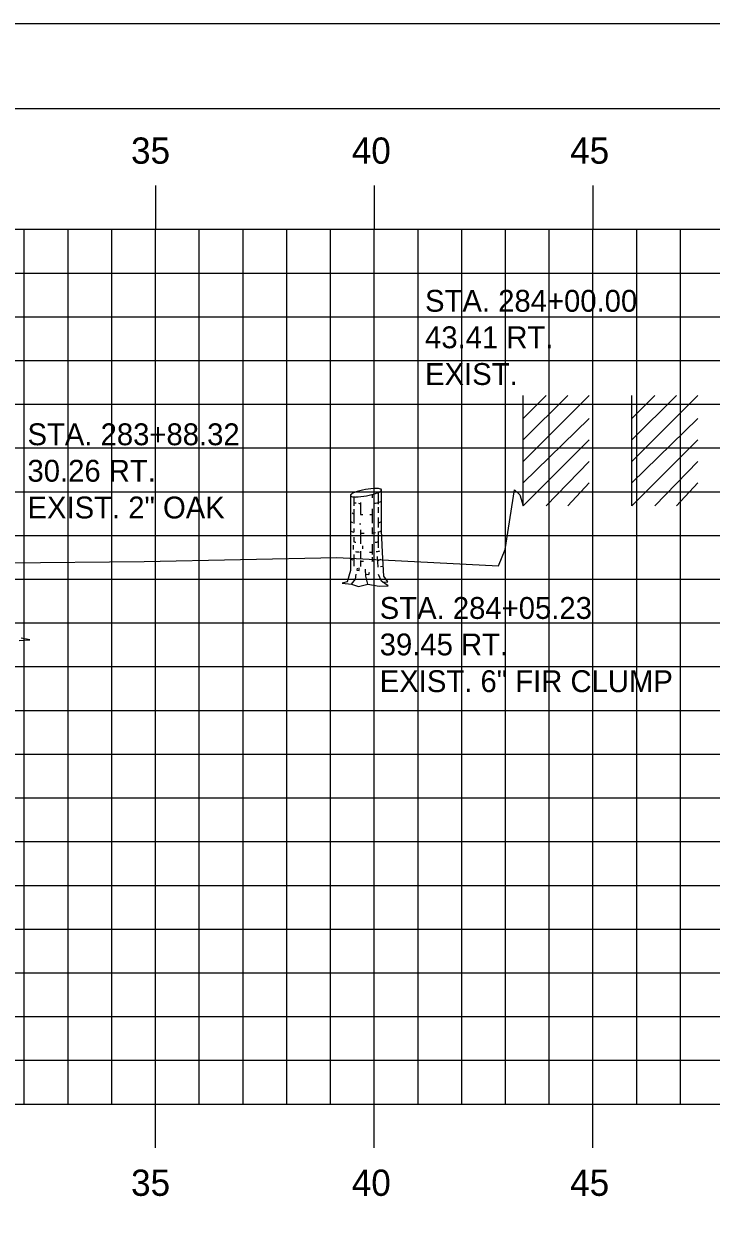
# Model space of a CAD drawing. Extents: x 856235 to 856405, y 366268 to 366378.
# Drawn here: x 856349.77 to 856365.48, y 366350.83 to 366378.18 of the extents above; entities that cross this region are included whole.
import ezdxf

# ---------------------------------------------------------------- set-up
doc = ezdxf.new("R2010")
doc.units = 0
for name, color, linetype in [('BORDER', 7, 'Continuous'), ('D_Text_Monospaced', 7, 'Continuous'), ('H_V ANNOTATION', 7, 'Continuous'), ('MAJOR', 7, 'Continuous'), ('MINOR', 7, 'Continuous'), ('PLOT BOUNDARY', 7, 'Continuous'), ('S_Buildings', 7, 'Continuous'), ('S_Roadway_Centerline', 7, 'Continuous'), ('S_Trees_Conifer_NonPay', 7, 'Continuous'), ('S_Trees_Decid_Pay', 7, 'Continuous')]:
    doc.layers.add(name, color=color, linetype=linetype)

msp = doc.modelspace()

# ---------------------------------------------------------------- linework, layer by layer
at = {"layer": 'BORDER'}
msp.add_line((856402.781, 366376.236), (856242.781, 366376.236), dxfattribs=at)
at = {"layer": 'MAJOR'}
for p, q in [((856352.781, 366374.483), (856352.781, 366373.481)), ((856357.781, 366374.483), (856357.781, 366373.481)), ((856362.781, 366374.483), (856362.781, 366373.481)), ((856247.781, 366373.481), (856387.781, 366373.481)), ((856247.781, 366373.481), (856387.781, 366373.481)), ((856352.781, 366353.481), (856352.781, 366373.481)), ((856357.781, 366353.481), (856357.781, 366373.481)), ((856362.781, 366353.481), (856362.781, 366373.481)), ((856247.781, 366368.481), (856387.781, 366368.481)), ((856247.781, 366363.481), (856387.781, 366363.481)), ((856247.781, 366358.481), (856387.781, 366358.481)), ((856247.781, 366353.481), (856387.781, 366353.481)), ((856247.781, 366353.481), (856387.781, 366353.481)), ((856352.781, 366352.479), (856352.781, 366353.481)), ((856357.781, 366352.479), (856357.781, 366353.481)), ((856362.781, 366352.479), (856362.781, 366353.481))]:
    msp.add_line(p, q, dxfattribs=at)
at = {"layer": 'MINOR'}
for p, q in [((856349.781, 366353.481), (856349.781, 366373.481)), ((856350.781, 366353.481), (856350.781, 366373.481)), ((856351.781, 366353.481), (856351.781, 366373.481)), ((856353.781, 366353.481), (856353.781, 366373.481)), ((856354.781, 366353.481), (856354.781, 366373.481)), ((856355.781, 366353.481), (856355.781, 366373.481)), ((856356.781, 366353.481), (856356.781, 366373.481)), ((856358.781, 366353.481), (856358.781, 366373.481)), ((856359.781, 366353.481), (856359.781, 366373.481)), ((856360.781, 366353.481), (856360.781, 366373.481)), ((856361.781, 366353.481), (856361.781, 366373.481)), ((856363.781, 366353.481), (856363.781, 366373.481)), ((856364.781, 366353.481), (856364.781, 366373.481)), ((856247.781, 366372.481), (856387.781, 366372.481)), ((856247.781, 366371.481), (856387.781, 366371.481)), ((856247.781, 366370.481), (856387.781, 366370.481)), ((856247.781, 366369.481), (856387.781, 366369.481)), ((856247.781, 366367.481), (856387.781, 366367.481)), ((856247.781, 366366.481), (856387.781, 366366.481)), ((856247.781, 366365.481), (856387.781, 366365.481)), ((856247.781, 366364.481), (856387.781, 366364.481)), ((856247.781, 366362.481), (856387.781, 366362.481)), ((856247.781, 366361.481), (856387.781, 366361.481)), ((856247.781, 366360.481), (856387.781, 366360.481)), ((856247.781, 366359.481), (856387.781, 366359.481)), ((856247.781, 366357.481), (856387.781, 366357.481)), ((856247.781, 366356.481), (856387.781, 366356.481)), ((856247.781, 366355.481), (856387.781, 366355.481)), ((856247.781, 366354.481), (856387.781, 366354.481))]:
    msp.add_line(p, q, dxfattribs=at)
at = {"layer": 'PLOT BOUNDARY'}
msp.add_lwpolyline([(856234.688, 366268.177), (856404.688, 366268.177), (856404.688, 366378.177), (856234.688, 366378.177)], close=True, dxfattribs=at)
at = {"layer": 'S_Buildings'}
for p, q in [((856361.186, 366367.157), (856361.186, 366369.683)), ((856361.186, 366368.174), (856362.696, 366369.683)), ((856361.186, 366368.666), (856362.203, 366369.683)), ((856361.186, 366369.158), (856361.711, 366369.683)), ((856363.672, 366367.157), (856363.672, 366369.683)), ((856363.672, 366368.174), (856365.182, 366369.683)), ((856363.672, 366368.666), (856364.69, 366369.683)), ((856363.672, 366369.158), (856364.197, 366369.683)), ((856361.186, 366367.682), (856362.696, 366369.158)), ((856363.672, 366367.682), (856365.182, 366369.158)), ((856361.186, 366367.157), (856362.696, 366368.666)), ((856363.672, 366367.157), (856365.182, 366368.666)), ((856361.711, 366367.157), (856362.696, 366368.174)), ((856364.197, 366367.157), (856365.182, 366368.174)), ((856362.203, 366367.157), (856362.696, 366367.682)), ((856364.69, 366367.157), (856365.182, 366367.682))]:
    msp.add_line(p, q, dxfattribs=at)
at = {"layer": 'S_Roadway_Centerline'}
msp.add_lwpolyline([(856328.954, 366363.708), (856329.863, 366363.704), (856333.689, 366363.627), (856333.914, 366363.825), (856333.97, 366363.951), (856334.308, 366364.232), (856334.342, 366364.246), (856335.581, 366364.715), (856337.467, 366365.5), (856349.355, 366365.853), (856352.52, 366365.887), (856356.926, 366365.979), (856360.623, 366365.787), (856360.773, 366366.162), (856360.989, 366367.526), (856361.112, 366367.411), (856361.186, 366367.157)], dxfattribs=at)
at = {"layer": 'S_Trees_Conifer_NonPay'}
for p, q in [((856357.314, 366367.362), (856357.314, 366367.156)), ((856357.47, 366367.237), (856357.47, 366366.964)), ((856357.732, 366367.417), (856357.732, 366367.338)), ((856357.314, 366367.084), (856357.314, 366366.752)), ((856357.732, 366367.089), (856357.732, 366366.763)), ((856357.867, 366367.128), (856357.867, 366366.998)), ((856357.314, 366366.638), (856357.314, 366366.559)), ((856357.732, 366366.662), (856357.732, 366366.509)), ((856357.867, 366366.889), (856357.867, 366366.662)), ((856357.314, 366366.445), (856357.314, 366366.336)), ((856357.47, 366366.61), (856357.47, 366366.292)), ((856357.867, 366366.571), (856357.867, 366366.195)), ((856357.297, 366366.258), (856357.297, 366366.161)), ((856357.47, 366366.122), (856357.47, 366365.962)), ((856357.512, 366366.247), (856357.512, 366366.177)), ((856357.732, 366366.28), (856357.732, 366366.047)), ((856357.314, 366366.047), (856357.314, 366365.779)), ((856357.47, 366365.905), (856357.47, 366365.773)), ((856357.732, 366365.985), (856357.732, 366365.899)), ((856357.848, 366366.002), (856357.866, 366365.756)), ((856357.927, 366365.773), (856357.988, 366365.78))]:
    msp.add_line(p, q, dxfattribs=at)
for points in [[(856357.867, 366367.458), (856357.867, 366367.361), (856357.867, 366367.196)], [(856357.978, 366365.412), (856358.094, 366365.422), (856358.002, 366365.547), (856357.969, 366366.088), (856357.948, 366366.605), (856357.948, 366367.524)], [(856357.235, 366367.396), (856357.235, 366365.678), (856357.165, 366365.422), (856357.046, 366365.387), (856357.262, 366365.371), (856357.422, 366365.313), (856357.631, 366365.371), (856357.894, 366365.324), (856358.1, 366365.33), (856357.948, 366365.433), (856357.877, 366365.586)], [(856357.262, 366365.371), (856357.352, 366365.483), (856357.369, 366365.597)], [(856357.394, 366365.734), (856357.383, 366365.689), (856357.433, 366365.678), (856357.433, 366365.74)], [(856357.631, 366365.371), (856357.587, 366365.547), (856357.581, 366365.712)], [(856357.585, 366365.597), (856357.654, 366365.592), (856357.673, 366365.644)]]:
    msp.add_lwpolyline(points, dxfattribs=at)
for centre, radius, start, end in [((856357.409, 366367.233), 0.245, 108.3946, 130.3798), ((856357.907, 366365.733), 1.825, 100.3798, 108.3946), ((856357.907, 366365.733), 1.825, 92.3651, 100.3798), ((856357.842, 366367.312), 0.245, 70.3798, 92.3651), ((856357.774, 366367.685), 0.245, 288.3946, 310.3798), ((856357.9, 366367.475), 0.0729, 59.1402, 70.3798), ((856357.886, 366367.554), 0.0729, 310.3798, 321.6195), ((856357.924, 366367.515), 0.0263, 40.3798, 59.1402), ((856357.922, 366367.525), 0.0263, 321.6195, 340.3798), ((856357.93, 366367.52), 0.0186, 26.433, 40.3798), ((856357.934, 366367.522), 0.0141, 10.3798, 26.433), ((856357.929, 366367.522), 0.0186, 340.3798, 354.3267), ((856357.934, 366367.522), 0.0141, 354.3267, 10.3798), ((856357.253, 366367.396), 0.0186, 160.3798, 174.3267), ((856357.249, 366367.396), 0.0141, 174.3267, 190.3798), ((856357.249, 366367.396), 0.0141, 190.3798, 206.433), ((856357.25, 366367.28), 0.0143, 180, 196.0515), ((856357.261, 366367.393), 0.0263, 141.6195, 160.3798), ((856357.253, 366367.398), 0.0186, 206.433, 220.3798), ((856357.259, 366367.403), 0.0263, 220.3798, 239.1402), ((856357.297, 366367.364), 0.0729, 130.3798, 141.6195), ((856357.283, 366367.443), 0.0729, 239.1402, 250.3798), ((856357.341, 366367.605), 0.245, 250.3798, 272.3651), ((856357.377, 366367.469), 0.245, 254.8461, 261.8968), ((856357.592, 366368.976), 1.767, 261.8968, 262.605), ((856357.275, 366369.184), 1.825, 272.3651, 280.3798), ((856357.592, 366368.976), 1.767, 264.3267, 266.0499), ((856357.275, 366369.184), 1.825, 280.3798, 288.3946), ((856357.592, 366368.976), 1.767, 276.2449, 278.1032), ((856357.807, 366367.469), 0.245, 278.1032, 284.1859), ((856357.807, 366367.469), 0.245, 291.7653, 300), ((856357.892, 366367.321), 0.0738, 300, 311.2506), ((856357.923, 366367.285), 0.0267, 311.2506, 330), ((856357.93, 366367.282), 0.0189, 330, 343.9485), ((856357.379, 366367.217), 0.245, 244.3148, 257.5375), ((856357.594, 366368.724), 1.767, 265.8991, 267.5962), ((856357.594, 366368.724), 1.767, 272.7221, 274.4847), ((856357.925, 366367.033), 0.0267, 311.2506, 330), ((856357.932, 366367.029), 0.0189, 330, 343.9485), ((856357.25, 366366.814), 0.0143, 180, 196.0515), ((856357.254, 366366.816), 0.0189, 196.0515, 210), ((856357.261, 366366.819), 0.0267, 210, 228.7494), ((856357.292, 366366.855), 0.0738, 228.7494, 240), ((856357.377, 366367.003), 0.245, 240, 246.7914), ((856357.377, 366367.003), 0.245, 254.8461, 257.5454), ((856357.592, 366368.51), 1.767, 265.2285, 266.1325), ((856357.807, 366367.003), 0.245, 284.1859, 300), ((856357.892, 366366.855), 0.0738, 300, 311.2506), ((856357.923, 366366.819), 0.0267, 311.2506, 330), ((856357.93, 366366.816), 0.0189, 330, 343.9485), ((856357.25, 366366.603), 0.0143, 180, 196.0515), ((856357.254, 366366.604), 0.0189, 196.0515, 210), ((856357.261, 366366.608), 0.0267, 210, 228.7494), ((856357.292, 366366.643), 0.0738, 228.7494, 240), ((856357.378, 366366.791), 0.245, 240, 254.9514), ((856357.592, 366368.299), 1.767, 266.0429, 268.5525), ((856357.592, 366368.299), 1.767, 274.5361, 277.0026), ((856357.807, 366366.791), 0.245, 292.1924, 300), ((856357.892, 366366.643), 0.0738, 300, 311.2506), ((856357.923, 366366.608), 0.0267, 311.2506, 330), ((856357.93, 366366.604), 0.0189, 330, 343.9485), ((856357.249, 366366.166), 0.0143, 180, 196.0515), ((856357.377, 366366.572), 0.245, 254.9814, 261.8968), ((856357.591, 366368.08), 1.767, 261.8968, 262.45), ((856357.591, 366367.862), 1.767, 262.2622, 265.0496), ((856357.591, 366367.862), 1.767, 272.6293, 274.5612), ((856357.591, 366368.08), 1.767, 276.7966, 278.1032), ((856357.591, 366367.862), 1.767, 277.63, 278.1032), ((856357.806, 366366.572), 0.245, 278.1032, 284.3207), ((856357.806, 366366.355), 0.245, 278.1032, 294.6056), ((856357.249, 366365.961), 0.0143, 180, 196.0515), ((856357.253, 366365.962), 0.0189, 196.0515, 210), ((856357.26, 366365.966), 0.0267, 210, 228.7494), ((856357.291, 366366.001), 0.0738, 228.7494, 240), ((856357.376, 366366.149), 0.245, 240, 249.1675), ((856357.591, 366367.657), 1.767, 266.0862, 268.2187), ((856357.591, 366367.657), 1.767, 274.2776, 276.3006), ((856357.806, 366366.149), 0.245, 284.0684, 300), ((856357.891, 366366.001), 0.0738, 300, 302.05)]:
    msp.add_arc(centre, radius, start, end, dxfattribs=at)
at = {"layer": 'S_Trees_Decid_Pay'}
msp.add_lwpolyline([(856349.662, 366364.08), (856349.903, 366364.092), (856349.705, 366364.129)], dxfattribs=at)

# ---------------------------------------------------------------- texts
at = {"layer": 'D_Text_Monospaced'}
for s, height, p in [('STA. 284+00.00', 0.49998, (856358.942, 366371.596)), ('43.41 RT.', 0.5, (856358.942, 366370.762)), ('EXIST. ', 0.5, (856358.942, 366369.922)), ('STA. 283+88.32', 0.49998, (856349.853, 366368.544)), ('30.26 RT.', 0.5, (856349.853, 366367.71)), ('EXIST. 2" OAK', 0.49998, (856349.853, 366366.87)), ('STA. 284+05.23', 0.49998, (856357.906, 366364.573)), ('39.45 RT.', 0.5, (856357.906, 366363.739)), ('EXIST. 6" FIR CLUMP', 0.49998, (856357.906, 366362.899))]:
    msp.add_text(s, height=height, dxfattribs=at).set_placement(p)
at = {"layer": 'H_V ANNOTATION'}
for s, p in [('35', (856352.221, 366374.981)), ('40', (856357.267, 366374.981)), ('45', (856362.259, 366374.981)), ('35', (856352.221, 366351.381)), ('40', (856357.267, 366351.381)), ('45', (856362.259, 366351.381))]:
    msp.add_text(s, height=0.6, dxfattribs=at).set_placement(p)

doc.saveas('drawing.dxf')
